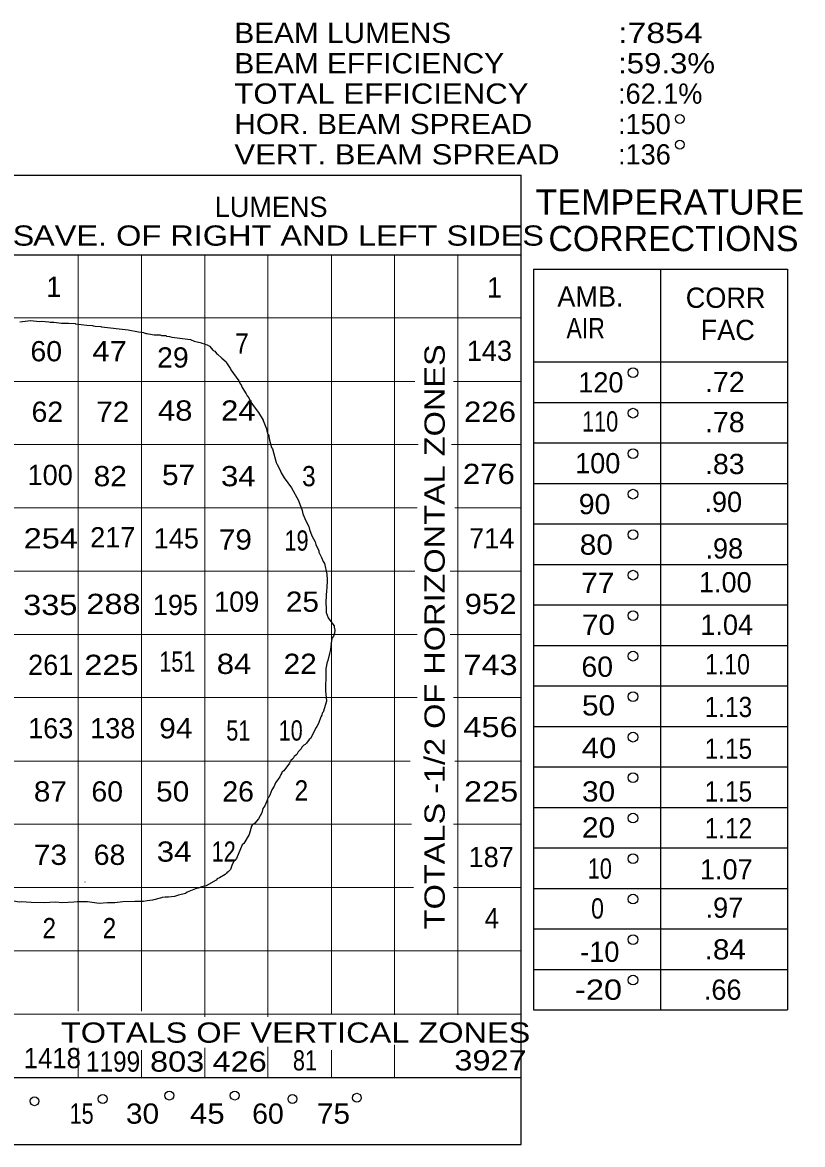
# Model space of a CAD drawing. Extents: x -39.6 to 16.1, y -17.6 to 34.
# Drawn here: x 11.49 to 15.34, y 19.46 to 25 of the extents above; entities that cross this region are included whole.
import ezdxf
from ezdxf.enums import TextEntityAlignment as Align

# ---------------------------------------------------------------- set-up
doc = ezdxf.new("R2010")
doc.units = 0
doc.header["$LTSCALE"] = 0.05
doc.layers.add('1', color=7, linetype='Continuous', lineweight=13)

msp = doc.modelspace()

# ---------------------------------------------------------------- linework, layer by layer
at = {"layer": '1', "lineweight": 25}
for p, q in [((8.95479, 24.24542), (13.95379, 24.24542)), ((13.95379, 19.45842), (13.95379, 24.24542)), ((9.26579, 23.85242), (13.95379, 23.85242)), ((14.01479, 23.78142), (15.26879, 23.78142)), ((14.01479, 23.78142), (14.01479, 20.12342)), ((14.64179, 23.78142), (14.64179, 20.12342)), ((15.26879, 23.78142), (15.26879, 20.12342)), ((14.01479, 23.32342), (15.26879, 23.32342)), ((14.01479, 23.12342), (15.26879, 23.12342)), ((14.01479, 22.92342), (15.26879, 22.92342)), ((14.01479, 22.72342), (15.26879, 22.72342)), ((14.01479, 22.52342), (15.26879, 22.52342)), ((14.01479, 22.32342), (15.26879, 22.32342)), ((14.01479, 22.12342), (15.26879, 22.12342)), ((14.01479, 21.92342), (15.26879, 21.92342)), ((14.01479, 21.72342), (15.26879, 21.72342)), ((14.01479, 21.52342), (15.26879, 21.52342)), ((14.01479, 21.32342), (15.26879, 21.32342)), ((14.01479, 21.12342), (15.26879, 21.12342)), ((14.01479, 20.92342), (15.26879, 20.92342)), ((11.80079, 20.75442), (11.79979, 20.75342)), ((14.01479, 20.72342), (15.26879, 20.72342)), ((14.01479, 20.52342), (15.26879, 20.52342)), ((14.01479, 20.32342), (15.26879, 20.32342)), ((14.01479, 20.12342), (15.26879, 20.12342)), ((9.26579, 19.78942), (13.95379, 19.78942)), ((8.95479, 19.45842), (13.95379, 19.45842))]:
    msp.add_line(p, q, dxfattribs=at)
at = {"layer": '1'}
for p, q in [((11.76679, 20.11642), (11.76679, 23.85242)), ((12.07879, 20.11642), (12.07879, 23.85242)), ((12.39179, 20.08842), (12.39179, 23.85242)), ((12.70379, 20.08842), (12.70379, 23.85242)), ((13.01679, 20.10542), (13.01679, 23.85242)), ((13.32879, 20.09942), (13.32879, 23.85242)), ((13.64179, 20.09942), (13.64179, 23.85242)), ((9.78779, 23.54042), (13.95379, 23.54042)), ((9.77679, 23.22742), (13.42879, 23.22742)), ((13.62079, 23.22742), (13.95379, 23.22742)), ((9.77679, 22.91542), (13.44479, 22.91542)), ((13.60979, 22.91542), (13.95379, 22.91542)), ((11.20379, 22.60242), (13.43979, 22.60242)), ((13.62579, 22.60242), (13.95379, 22.60242)), ((11.30979, 22.29042), (13.42879, 22.29042)), ((13.60379, 22.29042), (13.95379, 22.29042)), ((10.94179, 21.97742), (13.43979, 21.97742)), ((13.60379, 21.97742), (13.95379, 21.97742)), ((9.26579, 21.66542), (13.43979, 21.66542)), ((13.62079, 21.66542), (13.95379, 21.66542)), ((9.26579, 21.35242), (13.40679, 21.35242)), ((13.62579, 21.35242), (13.95379, 21.35242)), ((9.26579, 21.04042), (13.41179, 21.04042)), ((13.62079, 21.04042), (13.95379, 21.04042)), ((9.26579, 20.72742), (13.42279, 20.72742)), ((13.62079, 20.72742), (13.95379, 20.72742)), ((9.26579, 20.41542), (13.95379, 20.41542)), ((9.26579, 20.10242), (13.95379, 20.10242)), ((13.32879, 19.78942), (13.32879, 19.95142)), ((11.76679, 19.78942), (11.76679, 19.93542)), ((12.07879, 19.78942), (12.07879, 19.92442)), ((12.39179, 19.78942), (12.39179, 19.93542)), ((12.70379, 19.78942), (12.70379, 19.94042)), ((13.01679, 19.78942), (13.01679, 19.92442))]:
    msp.add_line(p, q, dxfattribs=at)
at = {"layer": '1', "lineweight": 25}
for points in [[(11.47879, 23.52142), (11.53179, 23.52742), (11.57579, 23.52342), (11.58479, 23.52442), (11.62079, 23.52142), (11.62879, 23.51942), (11.64579, 23.51942), (11.68479, 23.51442), (11.71879, 23.51542), (11.75179, 23.51342), (11.75379, 23.51142), (11.80979, 23.50442), (11.83679, 23.50342), (11.83979, 23.50142), (11.85079, 23.49942), (11.87779, 23.49842), (11.88179, 23.49742), (12.01279, 23.48142), (12.06479, 23.47242), (12.08879, 23.46942), (12.10079, 23.46442), (12.10779, 23.46442), (12.11379, 23.46142), (12.14179, 23.45742), (12.17079, 23.45742), (12.17879, 23.45442), (12.20079, 23.45342), (12.20279, 23.45142), (12.21679, 23.44942), (12.22879, 23.44542), (12.32179, 23.43342), (12.33979, 23.42642), (12.37479, 23.41842), (12.37679, 23.41642), (12.39079, 23.41342), (12.39679, 23.40942), (12.40279, 23.40842), (12.41579, 23.40142), (12.43379, 23.38042), (12.44079, 23.37642), (12.44979, 23.36442), (12.45379, 23.36242), (12.47579, 23.34142), (12.49679, 23.32442), (12.49879, 23.31842), (12.51879, 23.28942), (12.51979, 23.28442), (12.55979, 23.22942), (12.56679, 23.21542), (12.56979, 23.21342), (12.57679, 23.19642), (12.59579, 23.16642), (12.60079, 23.15542), (12.60879, 23.14542), (12.61879, 23.12442), (12.63579, 23.10142), (12.65679, 23.07342), (12.68079, 23.03642), (12.68079, 23.03342), (12.69679, 22.99242), (12.69779, 22.98342), (12.70379, 22.96742), (12.70579, 22.96442), (12.71179, 22.93742), (12.72179, 22.90142), (12.72579, 22.89342), (12.74379, 22.82742), (12.74979, 22.81742), (12.76279, 22.79142), (12.76879, 22.77542), (12.78379, 22.75042), (12.81979, 22.70242), (12.85479, 22.63942), (12.85679, 22.63442), (12.87279, 22.58942), (12.87579, 22.57342), (12.89079, 22.53842), (12.90479, 22.51042), (12.90879, 22.49542), (12.92079, 22.46442), (12.93679, 22.43542), (12.94079, 22.42142), (12.95479, 22.39042), (12.95479, 22.38442), (12.96879, 22.35742), (12.97679, 22.33742), (12.98279, 22.32742), (12.99379, 22.27542), (12.99579, 22.24742), (12.99379, 22.20542), (12.99279, 22.19642), (12.98979, 22.13842), (12.99079, 22.10142), (12.99079, 22.08542), (13.00179, 22.05942), (13.02879, 22.02142), (13.03079, 22.02142), (13.03079, 22.01342)], [(13.03079, 22.01342), (13.03379, 21.99942), (13.03179, 21.98342), (13.02679, 21.96942), (13.02079, 21.96042), (13.01679, 21.94742), (13.01579, 21.93242), (13.01479, 21.92742), (13.01579, 21.92542), (13.01379, 21.91942), (13.01279, 21.90242), (13.00779, 21.88342), (12.99879, 21.84842), (12.99379, 21.83642), (12.99079, 21.81442), (12.98879, 21.81042), (12.98979, 21.78742), (12.98779, 21.69842), (12.99279, 21.64842), (12.97679, 21.59442), (12.97179, 21.58942), (12.96979, 21.57842), (12.96479, 21.57042), (12.95379, 21.53842), (12.94579, 21.52342), (12.94179, 21.51842), (12.91379, 21.46442), (12.90779, 21.45942), (12.89479, 21.44142), (12.88779, 21.43442), (12.88079, 21.43142), (12.87179, 21.42142), (12.86779, 21.41342), (12.86179, 21.40642), (12.85279, 21.39842), (12.84579, 21.38542), (12.83379, 21.37442), (12.82879, 21.36542), (12.81679, 21.35442), (12.80979, 21.34242), (12.78179, 21.30442), (12.77179, 21.29742), (12.77179, 21.29442), (12.76679, 21.28542), (12.76179, 21.27442), (12.74079, 21.24542), (12.73479, 21.22842), (12.72279, 21.20942), (12.71379, 21.18442), (12.70879, 21.17442), (12.70379, 21.16942), (12.69879, 21.15342), (12.69379, 21.14342), (12.68879, 21.13042), (12.67879, 21.11742), (12.67379, 21.09742), (12.65679, 21.06742), (12.63879, 21.04542), (12.62779, 21.03842), (12.62279, 21.03142), (12.61079, 20.99042), (12.58379, 20.94442), (12.57679, 20.93842), (12.54779, 20.87042), (12.54079, 20.86142), (12.53279, 20.85542), (12.52579, 20.83642), (12.51879, 20.81742), (12.50479, 20.80342), (12.50179, 20.80342), (12.49879, 20.79842), (12.49179, 20.79242), (12.46379, 20.77542), (12.45279, 20.77142), (12.44779, 20.76442), (12.39779, 20.73642), (12.37679, 20.73142), (12.35979, 20.72442), (12.34579, 20.72142), (12.30479, 20.70442), (12.29579, 20.69842), (12.26179, 20.69042), (12.24279, 20.68342), (12.21279, 20.67942), (12.20479, 20.68042), (12.19579, 20.67942), (12.18179, 20.67842), (12.17879, 20.67642), (12.13379, 20.66542), (12.10779, 20.66242), (12.08979, 20.65842), (12.04579, 20.65942), (11.98679, 20.65642), (11.94779, 20.65242), (11.91079, 20.65242), (11.87079, 20.64942), (11.81179, 20.65642), (11.76079, 20.65742), (11.74579, 20.65542), (11.68979, 20.65242), (11.65479, 20.65542)], [(11.65479, 20.65542), (11.59879, 20.65142), (11.53479, 20.65342), (11.48479, 20.65642), (11.47479, 20.65542), (11.44779, 20.66042), (11.44579, 20.66042)]]:
    msp.add_lwpolyline(points, dxfattribs=at)
for centre, radius in [((14.73779, 24.52342), 0.022), ((14.73779, 24.39642), 0.022), ((14.50679, 23.27042), 0.024), ((14.50679, 23.07042), 0.024), ((14.50679, 22.87042), 0.024), ((14.50679, 22.67042), 0.024), ((14.50679, 22.47042), 0.024), ((14.50679, 22.27042), 0.024), ((14.50679, 22.07042), 0.024), ((14.50679, 21.87042), 0.024), ((14.50679, 21.67042), 0.024), ((14.50679, 21.47042), 0.024), ((14.50679, 21.27042), 0.024), ((14.50679, 21.07042), 0.024), ((14.50679, 20.87042), 0.024), ((14.50679, 20.67042), 0.024), ((14.50679, 20.47042), 0.024), ((14.50679, 20.27042), 0.024), ((11.55079, 19.67242), 0.022), ((11.88779, 19.68342), 0.022), ((12.21679, 19.70042), 0.022), ((12.53979, 19.70042), 0.022), ((12.82479, 19.68342), 0.022), ((13.14279, 19.68942), 0.022)]:
    msp.add_circle(centre, radius, dxfattribs=at)

# ---------------------------------------------------------------- texts
at = {"layer": '1'}
for s, width, p in [('BEAM LUMENS', 1.1, (12.53779, 24.89842)), (':7854', 1.25, (14.43279, 24.89842)), ('BEAM EFFICIENCY', 1.1, (12.53779, 24.74842)), (':59.3%', 1.15, (14.43279, 24.74842)), ('TOTAL EFFICIENCY', 1.15, (12.53779, 24.59842)), ('HOR. BEAM SPREAD', 1.1, (12.53779, 24.44842)), ('VERT. BEAM SPREAD', 1.15, (12.53779, 24.29842))]:
    msp.add_text(s, height=0.1, dxfattribs=dict(at, width=width)).set_placement(p)
for s, p in [(':62.1%', (14.43279, 24.59842)), (':150', (14.43279, 24.44842)), (':136', (14.43279, 24.29842))]:
    msp.add_text(s, height=0.1, dxfattribs=at).set_placement(p)
for s, height, width, p in [('TEMPERATURE', 0.125, 1.05, (14.68829, 24.05042)), ('AVE. OF RIGHT AND LEFT SIDES', 0.1, 1.2, (10.28829, 23.89742)), ('AVE. OF RIGHT AND LEFT SIDES', 0.1, 1.2, (12.80529, 23.89742)), ('AIR', 0.1, 0.85, (14.27279, 23.44042)), ('7', 0.1, 0.9, (12.57529, 23.36442)), ('60', 0.1, 1.05, (11.60879, 23.32642)), ('47', 0.1, 1.15, (11.92179, 23.32642)), ('29', 0.1, 1.05, (12.23429, 23.29542)), ('.72', 0.1, 1.05, (14.96029, 23.17442)), ('62', 0.1, 1.05, (11.61429, 23.02742)), ('72', 0.1, 1.1, (11.93729, 23.02742)), ('48', 0.1, 1.15, (12.24529, 23.03342)), ('24', 0.1, 1.15, (12.55729, 23.03342)), ('226', 0.1, 1.15, (13.80029, 23.02742)), ('110', 0.1, 0.8, (14.34429, 22.97942)), ('.78', 0.1, 1.05, (14.96029, 22.97642)), ('.83', 0.1, 1.05, (14.95979, 22.76942)), ('82', 0.1, 1.1, (11.92479, 22.70942)), ('57', 0.1, 1.1, (12.26229, 22.71542)), ('34', 0.1, 1.15, (12.55729, 22.70942)), ('3', 0.1, 0.9, (12.90579, 22.70942)), ('276', 0.1, 1.15, (13.79479, 22.72042)), ('90', 0.1, 1.05, (14.31679, 22.57142)), ('254', 0.1, 1.2, (11.63129, 22.40242)), ('79', 0.1, 1.1, (12.54279, 22.39642)), ('19', 0.1, 0.8, (12.84479, 22.39142)), ('80', 0.1, 1.1, (14.32529, 22.37142)), ('77', 0.1, 1.1, (14.33279, 22.18242)), ('335', 0.1, 1.2, (11.62879, 22.07342)), ('288', 0.1, 1.2, (11.94079, 22.07842)), ('25', 0.1, 1.1, (12.87379, 22.08942)), ('952', 0.1, 1.15, (13.80329, 22.07842)), ('70', 0.1, 1.1, (14.33579, 21.97542)), ('151', 0.1, 0.8, (12.25629, 21.79342)), ('225', 0.1, 1.2, (11.93079, 21.77742)), ('84', 0.1, 1.15, (12.53629, 21.78242)), ('22', 0.1, 1.1, (12.86279, 21.78242)), ('743', 0.1, 1.2, (13.80279, 21.77742)), ('60', 0.1, 1.05, (14.32979, 21.76842)), ('1.10', 0.1, 0.85, (14.97329, 21.78042)), ('50', 0.1, 1.1, (14.33629, 21.57742)), ('1.13', 0.1, 0.9, (14.97779, 21.56942)), ('94', 0.1, 1.1, (12.24879, 21.46442)), ('456', 0.1, 1.2, (13.80279, 21.47042)), ('51', 0.1, 0.8, (12.55729, 21.45342)), ('10', 0.1, 0.8, (12.81579, 21.45342)), ('40', 0.1, 1.15, (14.33879, 21.36742)), ('1.15', 0.1, 0.9, (14.97779, 21.36342)), ('87', 0.1, 1.1, (11.62929, 21.15242)), ('60', 0.1, 1.05, (11.90979, 21.15242)), ('50', 0.1, 1.1, (12.23329, 21.15242)), ('26', 0.1, 1.05, (12.55629, 21.15242)), ('2', 0.1, 0.9, (12.86879, 21.15742)), ('225', 0.1, 1.2, (13.80579, 21.15242)), ('30', 0.1, 1.1, (14.33629, 21.15242)), ('1.15', 0.1, 0.9, (14.97779, 21.15242)), ('20', 0.1, 1.1, (14.33629, 20.97442)), ('1.12', 0.1, 0.9, (14.97779, 20.97042)), ('34', 0.1, 1.15, (12.24029, 20.85542)), ('12', 0.1, 0.8, (12.48529, 20.85542)), ('73', 0.1, 1.1, (11.62929, 20.83942)), ('68', 0.1, 1.05, (11.92129, 20.83942)), ('10', 0.1, 0.8, (14.34279, 20.77142)), ('0', 0.1, 0.85, (14.33129, 20.57442)), ('4', 0.1, 0.95, (13.80929, 20.52642)), ('2', 0.1, 0.9, (11.62379, 20.47742)), ('2', 0.1, 0.9, (11.92079, 20.47742)), ('.84', 0.1, 1.1, (14.96229, 20.37242)), ('-20', 0.1, 1.2, (14.33629, 20.17342)), ('TOTALS OF VERTICAL ZONES', 0.1, 1.2, (12.84029, 19.96142)), ('1418', 0.1, 0.95, (11.63879, 19.83542)), ('1199', 0.1, 0.9, (11.93879, 19.81842)), ('803', 0.1, 1.2, (12.25529, 19.81842)), ('426', 0.1, 1.2, (12.56379, 19.81842)), ('81', 0.1, 0.8, (12.88629, 19.82442)), ('3927', 0.1, 1.2, (13.80279, 19.82442)), ('15', 0.1, 0.8, (11.78329, 19.56142)), ('30', 0.1, 1.1, (12.08429, 19.56142)), ('45', 0.1, 1.15, (12.40429, 19.56142)), ('60', 0.1, 1.05, (12.70379, 19.56142)), ('75', 0.1, 1.1, (13.02729, 19.56142))]:
    msp.add_text(s, height=height, dxfattribs=dict(at, width=width)).set_placement(p, align=Align.CENTER)
for s, height, p in [('LUMENS', 0.1, (12.71929, 24.03942)), ('CORRECTIONS', 0.125, (14.70629, 23.87042)), ('1', 0.1, (11.6463, 23.64442)), ('1', 0.1, (13.8223, 23.64142)), ('AMB.', 0.1, (14.29629, 23.59642)), ('CORR', 0.1, (14.96379, 23.59042)), ('FAC', 0.1, (14.97429, 23.43142)), ('143', 0.1, (13.79729, 23.32842)), ('120', 0.1, (14.34779, 23.17242)), ('100', 0.1, (14.33229, 22.77342)), ('100', 0.1, (11.62829, 22.71542)), ('.90', 0.1, (14.95229, 22.58242)), ('217', 0.1, (11.93729, 22.40742)), ('145', 0.1, (12.25129, 22.40242)), ('714', 0.1, (13.80879, 22.40242)), ('.98', 0.1, (14.95729, 22.35242)), ('1.00', 0.1, (14.96229, 22.18542)), ('195', 0.1, (12.24679, 22.07342)), ('109', 0.1, (12.54929, 22.08942)), ('1.04', 0.1, (14.96929, 21.97542)), ('261', 0.1, (11.63079, 21.77742)), ('163', 0.1, (11.63079, 21.46442)), ('138', 0.1, (11.93729, 21.46442)), ('187', 0.1, (13.80629, 20.82842)), ('1.07', 0.1, (14.96729, 20.76742)), ('.97', 0.1, (14.95779, 20.57842)), ('-10', 0.1, (14.34279, 20.36042)), ('.66', 0.1, (14.94929, 20.17342))]:
    msp.add_text(s, height=height, dxfattribs=at).set_placement(p, align=Align.CENTER)
at = {"layer": '1', "width": 1.2}
msp.add_text('TOTALS -1/2 OF HORIZONTAL ZONES', height=0.1, rotation=90, dxfattribs=at).set_placement((13.57679, 21.96592), align=Align.CENTER)

doc.saveas('drawing.dxf')
